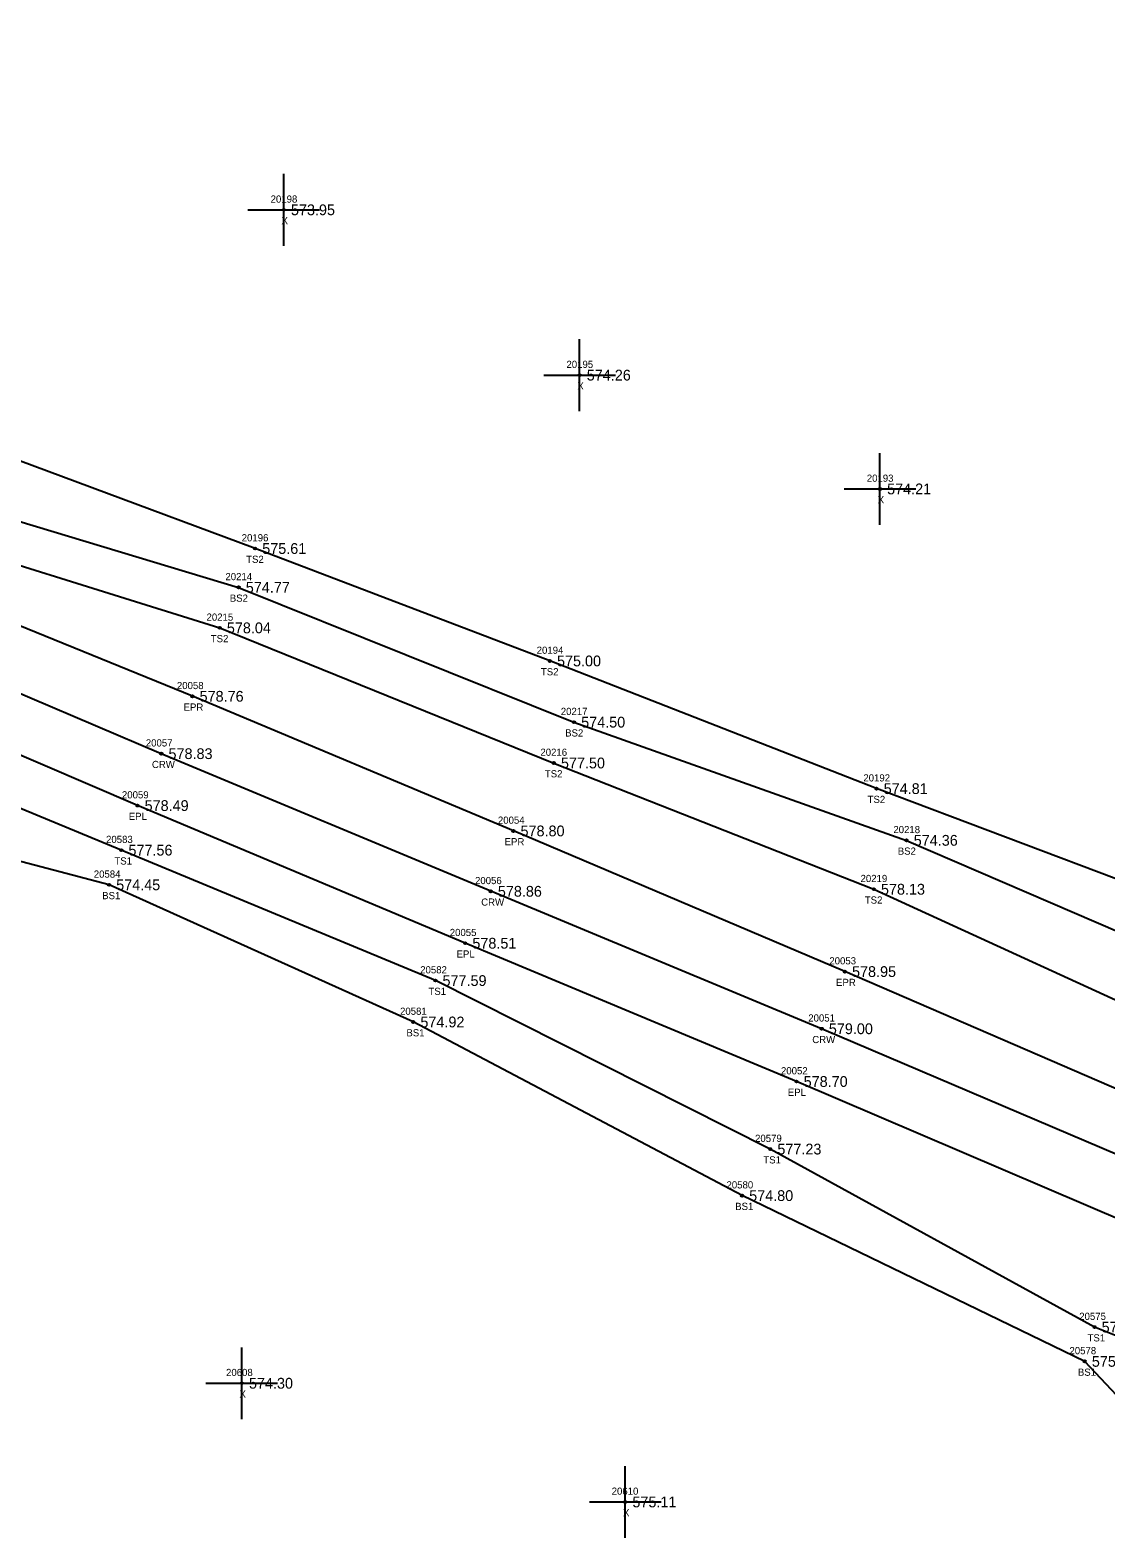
# Model space of a CAD drawing. Extents: x 1664837 to 1666270, y 987403 to 988245.
# Drawn here: x 1665313 to 1665462.9, y 987730.3 to 987940.3 of the extents above; entities that cross this region are included whole.
import ezdxf

# ---------------------------------------------------------------- set-up
doc = ezdxf.new("R2010")
doc.units = 0
for name, color, linetype in [('RD_DTM_BkLn1', 7, 'Continuous'), ('RD_DTM_BkLn2', 7, 'Continuous'), ('RD_DTM_BkLn_txCode', 7, 'Continuous'), ('RD_EX_Misc', 7, 'Continuous'), ('RD_EX_Misc_txCode', 7, 'Continuous'), ('RD_EX_Road', 7, 'Continuous'), ('RD_EX_Road_txCode', 7, 'Continuous'), ('RD_EX_TX_Misc_ELEV', 7, 'Continuous'), ('RD_EX_TX_Road_ELEV', 7, 'Continuous'), ('RD_HC_Survey_ELEV', 7, 'Continuous'), ('RD_HC_Survey_txCode', 7, 'Continuous'), ('RD_SMD_Locator', 7, 'Continuous')]:
    doc.layers.add(name, color=color, linetype=linetype)

msp = doc.modelspace()

# ---------------------------------------------------------------- linework, layer by layer
at = {"layer": 'RD_DTM_BkLn1'}
msp.add_lwpolyline([(1665502.18, 987767.43), (1665469.18, 987781.68), (1665423.29, 987801.23), (1665377.17, 987820.37), (1665331.28, 987839.54), (1665285.44, 987859.03), (1665239.3, 987878.58), (1665193.14, 987897.86), (1665147.41, 987917.57), (1665101.07, 987936.7), (1665055.19, 987956.08), (1665009.23, 987975.83), (1664963.42, 987995.66), (1664917.15, 988015.07), (1664871.41, 988034.69)], dxfattribs=at)
at = {"layer": 'RD_DTM_BkLn2'}
for points in [[(1665526.5, 987797.57), (1665466.88, 987821.13), (1665430.93, 987834.67), (1665385.41, 987852.45), (1665344.34, 987868.11), (1665298.9, 987885.03), (1665253.91, 987902.76), (1665220.99, 987915.86), (1665188.5, 987922.98), (1665151.7, 987937.17), (1665150.15, 987932.64), (1665154.49, 987927.34), (1665198.68, 987910.11), (1665245.58, 987892.26), (1665291.48, 987872.02), (1665339.41, 987857.06), (1665385.96, 987838.24), (1665430.55, 987820.66), (1665476.41, 987799.7), (1665510.35, 987785.06), (1665506.66, 987778.89)], [(1665151.94, 987933.71), (1665201.46, 987914.66), (1665247.51, 987895.52), (1665294.62, 987876.98), (1665342.05, 987862.7), (1665388.78, 987843.93), (1665435.12, 987827.47), (1665481.62, 987807.44), (1665516.85, 987790.52)], [(1665497.35, 987756.86), (1665493.15, 987755.47), (1665489.09, 987748.98), (1665474.07, 987754.55), (1665461.3, 987759.68), (1665416.12, 987784.47), (1665369.46, 987807.94), (1665325.7, 987826.1), (1665279.41, 987845.24), (1665231.91, 987860.98), (1665183.47, 987888.09), (1665142.67, 987907.67), (1665119.08, 987916.32), (1665106.25, 987916.18)], [(1665485.84, 987738.32), (1665468.07, 987746.27), (1665459.94, 987754.9), (1665412.19, 987777.99), (1665366.38, 987802.17), (1665323.99, 987821.27), (1665274.79, 987834.22), (1665225.63, 987853.6), (1665180.43, 987876.62), (1665166.98, 987883.63), (1665152.71, 987895.52), (1665118.68, 987912.3), (1665108.44, 987911.82), (1665107.08, 987900.15)]]:
    msp.add_lwpolyline(points, dxfattribs=at)
at = {"layer": 'RD_EX_Misc'}
for p, q in [((1665348.34, 987910.28), (1665348.34, 987920.28)), ((1665343.34, 987915.28), (1665353.34, 987915.28)), ((1665389.56, 987887.26), (1665389.56, 987897.26)), ((1665384.56, 987892.26), (1665394.56, 987892.26)), ((1665431.41, 987871.41), (1665431.41, 987881.41)), ((1665426.41, 987876.41), (1665436.41, 987876.41)), ((1665342.49, 987746.86), (1665342.49, 987756.86)), ((1665337.49, 987751.86), (1665347.49, 987751.86)), ((1665395.92, 987730.33), (1665395.92, 987740.33)), ((1665390.92, 987735.33), (1665400.92, 987735.33))]:
    msp.add_line(p, q, dxfattribs=at)
at = {"layer": 'RD_EX_Road'}
for points in [[(1665506.06, 987776.52), (1665471.95, 987789.57), (1665426.52, 987809.19), (1665380.33, 987828.78), (1665335.61, 987847.53), (1665288.25, 987866.82), (1665242.34, 987886.56), (1665197.07, 987906.16), (1665152.2, 987925.43), (1665127.55, 987936.7), (1665104.5, 987945.2), (1665059.19, 987965.3), (1665013.63, 987984.66), (1664966.38, 988005.06), (1664921.66, 988023.83), (1664875.55, 988043.8)], [(1665498.75, 987759.37), (1665465.87, 987774.2), (1665419.78, 987793.88), (1665373.62, 987813.14), (1665327.95, 987832.31), (1665281.42, 987852.3), (1665236.13, 987871.34), (1665189.6, 987890.71), (1665143.92, 987909.97), (1665117.43, 987920.99), (1665086.22, 987934.27), (1665051.62, 987948.55), (1665005.38, 987968.44), (1664960.17, 987987.67), (1664913.53, 988007.62), (1664868.21, 988026.81)]]:
    msp.add_lwpolyline(points, dxfattribs=at)
at = {"layer": 'RD_SMD_Locator'}
for centre in [(1665348.34, 987915.28), (1665389.56, 987892.26), (1665431.41, 987876.41), (1665344.34, 987868.11), (1665342.05, 987862.7), (1665339.41, 987857.06), (1665385.41, 987852.45), (1665335.61, 987847.53), (1665388.78, 987843.93), (1665331.28, 987839.54), (1665385.96, 987838.24), (1665430.93, 987834.67), (1665327.95, 987832.31), (1665380.33, 987828.78), (1665435.12, 987827.47), (1665325.7, 987826.1), (1665323.99, 987821.27), (1665377.17, 987820.37), (1665430.55, 987820.66), (1665373.62, 987813.14), (1665426.52, 987809.19), (1665369.46, 987807.94), (1665366.38, 987802.17), (1665423.29, 987801.23), (1665419.78, 987793.88), (1665416.12, 987784.47), (1665412.19, 987777.99), (1665461.3, 987759.68), (1665459.94, 987754.9), (1665342.49, 987751.86), (1665395.92, 987735.33)]:
    msp.add_circle(centre, 0.15, dxfattribs=at)

# ---------------------------------------------------------------- texts
at = {"layer": 'RD_DTM_BkLn_txCode'}
for s, p in [('20196', (1665342.48, 987869.11)), ('TS2', (1665343.1, 987866.11)), ('20214', (1665340.21, 987863.7)), ('BS2', (1665340.82, 987860.7)), ('20215', (1665337.58, 987858.06)), ('TS2', (1665338.17, 987855.06)), ('20194', (1665383.58, 987853.45)), ('TS2', (1665384.17, 987850.45)), ('20217', (1665386.94, 987844.93)), ('BS2', (1665387.55, 987841.93)), ('20216', (1665384.1, 987839.24)), ('TS2', (1665384.72, 987836.24)), ('20192', (1665429.1, 987835.67)), ('TS2', (1665429.69, 987832.67)), ('20583', (1665323.58, 987827.1)), ('20218', (1665433.28, 987828.47)), ('BS2', (1665433.89, 987825.47)), ('20584', (1665321.87, 987822.27)), ('TS1', (1665324.74, 987824.1)), ('20219', (1665428.71, 987821.66)), ('BS1', (1665323.04, 987819.27)), ('TS2', (1665429.3, 987818.66)), ('20582', (1665367.35, 987808.94)), ('TS1', (1665368.5, 987805.94)), ('20581', (1665364.54, 987803.17)), ('BS1', (1665365.43, 987800.17)), ('20579', (1665414.01, 987785.47)), ('TS1', (1665415.16, 987782.47)), ('20580', (1665410.03, 987778.99)), ('BS1', (1665411.24, 987775.99)), ('20575', (1665459.18, 987760.68)), ('TS1', (1665460.34, 987757.68)), ('20578', (1665457.82, 987755.9)), ('BS1', (1665458.99, 987752.9))]:
    msp.add_text(s, height=1, dxfattribs=at).set_placement(p)
at = {"layer": 'RD_EX_Misc_txCode'}
for s, p in [('20198', (1665346.51, 987916.28)), ('X', (1665348.03, 987913.28)), ('20195', (1665387.73, 987893.26)), ('X', (1665389.25, 987890.26)), ('20193', (1665429.58, 987877.41)), ('X', (1665431.1, 987874.41)), ('20608', (1665340.3, 987752.86)), ('X', (1665342.17, 987749.86)), ('20610', (1665394.03, 987736.33)), ('X', (1665395.61, 987733.33))]:
    msp.add_text(s, height=1, dxfattribs=at).set_placement(p)
at = {"layer": 'RD_EX_Road_txCode'}
for s, p in [('20058', (1665333.45, 987848.53)), ('EPR', (1665334.38, 987845.53)), ('20059', (1665325.79, 987833.31)), ('EPL', (1665326.74, 987830.31)), ('20054', (1665378.18, 987829.78)), ('EPR', (1665379.11, 987826.78)), ('20055', (1665371.47, 987814.14)), ('EPL', (1665372.42, 987811.14)), ('20053', (1665424.36, 987810.19)), ('EPR', (1665425.29, 987807.19)), ('20052', (1665417.62, 987794.88)), ('EPL', (1665418.57, 987791.88))]:
    msp.add_text(s, height=1, dxfattribs=at).set_placement(p)
at = {"layer": 'RD_EX_TX_Misc_ELEV'}
for s, p in [('573.95', (1665349.34, 987914.53)), ('574.26', (1665390.56, 987891.51)), ('574.21', (1665432.41, 987875.66)), ('575.61', (1665345.34, 987867.36)), ('574.77', (1665343.05, 987861.95)), ('578.04', (1665340.41, 987856.31)), ('575.00', (1665386.41, 987851.7)), ('574.50', (1665389.78, 987843.18)), ('577.50', (1665386.96, 987837.49)), ('574.81', (1665431.93, 987833.92)), ('574.36', (1665436.12, 987826.72)), ('577.56', (1665326.7, 987825.35)), ('574.45', (1665324.99, 987820.52)), ('578.13', (1665431.55, 987819.91)), ('577.59', (1665370.46, 987807.19)), ('574.92', (1665367.38, 987801.42)), ('577.23', (1665417.12, 987783.72)), ('574.80', (1665413.19, 987777.24)), ('577.18', (1665462.3, 987758.93)), ('575.01', (1665460.94, 987754.15)), ('574.30', (1665343.49, 987751.11)), ('575.11', (1665396.92, 987734.58))]:
    msp.add_text(s, height=1.5, dxfattribs=at).set_placement(p)
at = {"layer": 'RD_EX_TX_Road_ELEV'}
for s, p in [('578.76', (1665336.61, 987846.78)), ('578.49', (1665328.95, 987831.56)), ('578.80', (1665381.33, 987828.03)), ('578.51', (1665374.62, 987812.39)), ('578.95', (1665427.52, 987808.44)), ('578.70', (1665420.78, 987793.13))]:
    msp.add_text(s, height=1.5, dxfattribs=at).set_placement(p)
at = {"layer": 'RD_HC_Survey_ELEV'}
for s, p in [('578.83', (1665332.28, 987838.79)), ('578.86', (1665378.17, 987819.62)), ('579.00', (1665424.29, 987800.48))]:
    msp.add_text(s, height=1.5, dxfattribs=at).set_placement(p)
at = {"layer": 'RD_HC_Survey_txCode'}
for s, p in [('20057', (1665329.12, 987840.54)), ('CRW', (1665329.97, 987837.54)), ('20056', (1665374.99, 987821.37)), ('CRW', (1665375.85, 987818.37)), ('20051', (1665421.42, 987802.23)), ('CRW', (1665421.98, 987799.23))]:
    msp.add_text(s, height=1, dxfattribs=at).set_placement(p)

doc.saveas('drawing.dxf')
